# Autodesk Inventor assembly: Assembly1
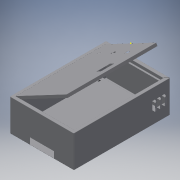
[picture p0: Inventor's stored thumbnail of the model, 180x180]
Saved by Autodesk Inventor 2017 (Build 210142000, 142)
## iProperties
Created: 2022-04
Part Number: Assembly1
Document SubType Name: Assembly
Designer: phat
Author: phat
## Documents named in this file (6)
- D:\inventor\cac ban ve\TỦ ĐIỆN\Assembly1.iam
- D:\inventor\cac ban ve\vo tu.ipt
- D:\inventor\cac ban ve\canh tu.ipt
- D:\inventor\cac ban ve\panel thiet bi.ipt
- D:\inventor\cac ban ve\bulong bat panel thiet bi.ipt
- D:\inventor\cac ban ve\chốt cánh cửa.ipt
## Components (9 placed, 5 different names)
1. vo tu:1 — Insert:1, Insert:2, Insert:3, Insert:4, Insert:7, Insert:8, Insert:9
2. canh tu:1 — Insert:9
3. panel thiet bi:1 — Insert:5, Insert:6
4. bulong bat panel thiet bi:1 — Insert:1, Insert:5
5. bulong bat panel thiet bi:2 — Insert:2, Insert:6
6. bulong bat panel thiet bi:3 — Insert:3
7. bulong bat panel thiet bi:4 — Insert:4
8. chốt cánh cửa:2 — Insert:8
9. chốt cánh cửa:3 — Insert:7
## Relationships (9: Insert 9)
- Insert:1: vo tu:1 ↔ bulong bat panel thiet bi:1
- Insert:2: vo tu:1 ↔ bulong bat panel thiet bi:2
- Insert:3: vo tu:1 ↔ bulong bat panel thiet bi:3
- Insert:4: vo tu:1 ↔ bulong bat panel thiet bi:4
- Insert:5: panel thiet bi:1 ↔ bulong bat panel thiet bi:1
- Insert:6: panel thiet bi:1 ↔ bulong bat panel thiet bi:2
- Insert:7: vo tu:1 ↔ chốt cánh cửa:3
- Insert:8: vo tu:1 ↔ chốt cánh cửa:2
- Insert:9: vo tu:1 ↔ canh tu:1
